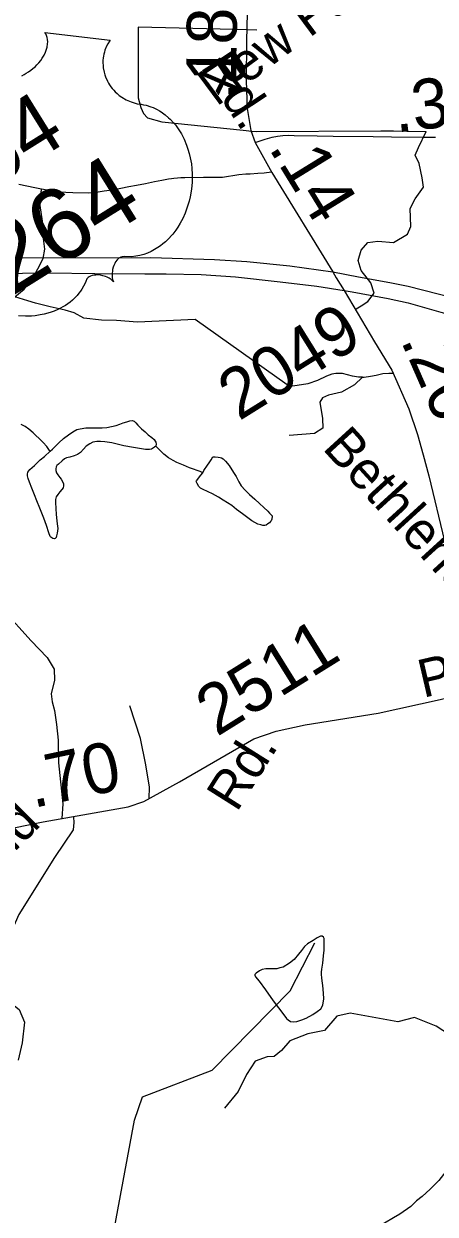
# Model space of a CAD drawing. Extents: x 2001466 to 31450019, y -30647475 to 847247.
# Drawn here: x 2150565 to 2152625, y 729877 to 735833 of the extents above; entities that cross this region are included whole.
import ezdxf

# ---------------------------------------------------------------- set-up
doc = ezdxf.new("R2010")
doc.units = 0
for name, color, linetype in [('Exist Hydrographic Misc Water Feature', 7, 'Continuous'), ('Exist Road Non-System Type 51', 7, 'Continuous'), ('Exist Road Non-System Type 51 Label', 7, 'Continuous'), ('Exist Road Primary US Divided Attributed', 7, 'Continuous'), ('Exist Road Primary US Shield CELL', 7, 'Continuous'), ('Exist Road Primary US Shield Number Label', 7, 'Continuous'), ('Exist Road Secondary Mileage Hundredths English Label', 7, 'Continuous'), ('Exist Road Secondary Type 51 Attributed', 7, 'Continuous'), ('Exist Road Secondary Type 51 Label', 7, 'Continuous'), ('Exist Road Secondary Type 51 Number Label', 7, 'Continuous')]:
    doc.layers.add(name, color=color, linetype=linetype)

msp = doc.modelspace()

# ---------------------------------------------------------------- linework, layer by layer
at = {"layer": 'Exist Hydrographic Misc Water Feature'}
for points in [[(2150696.8, 733694.2), (2150708.7, 733704.6), (2150740.9, 733736.6), (2150764.4, 733758.6), (2150788.4, 733776.9), (2150810.2, 733791.1), (2150830.1, 733803.1), (2150848.3, 733807.2), (2150876.2, 733811.5), (2150938.3, 733811.8), (2150958.2, 733811.7), (2150980.4, 733814), (2151004.4, 733818.1), (2151027.9, 733824.2), (2151046, 733830.5), (2151062.2, 733836.5), (2151081.9, 733842.4), (2151096.2, 733846.4), (2151107.9, 733848.6), (2151118, 733844.7), (2151125.9, 733836.6), (2151136, 733825), (2151154.2, 733806.8), (2151172.3, 733791.1), (2151188.3, 733777.3), (2151206.3, 733763.2), (2151218.4, 733753.3), (2151222.5, 733745.4), (2151226.2, 733739.5), (2151228.5, 733729.5), (2151226.4, 733719.6)], [(2150696.8, 733694.2), (2150694.9, 733698.2), (2150680.8, 733718.2), (2150662.9, 733737.9), (2150642.4, 733758.1), (2150626.4, 733773.9), (2150612.7, 733786.1), (2150590.4, 733805.6), (2150572.5, 733817.7), (2150552.4, 733827.6)], [(2151226.4, 733719.6), (2151220.5, 733715.2), (2151204.9, 733705.4), (2151194.6, 733703.3), (2151174.7, 733703.1), (2151114.7, 733712.6), (2151066.5, 733722.3), (2151006.8, 733736.2), (2150970.3, 733741.7), (2150950.2, 733743.9), (2150930.7, 733743.7), (2150910.4, 733739.4), (2150896.7, 733731.3), (2150877, 733719.3), (2150864.9, 733705.3), (2150848.9, 733689.1), (2150835, 733679), (2150817.1, 733671.2), (2150795.2, 733664.8), (2150778.8, 733660.8), (2150768.7, 733657), (2150757.3, 733646.6), (2150739.4, 733630.6), (2150731.2, 733622.5), (2150727.3, 733616.6), (2150725.7, 733606.7), (2150725.5, 733598.6), (2150729.4, 733586.7), (2150735.5, 733576.9), (2150745.8, 733562.7), (2150751.7, 733554.5), (2150763.8, 733532.8), (2150764, 733528.7), (2150764, 733521), (2150762, 733510.8), (2150755.8, 733502.8), (2150745.8, 733490.9), (2150736.6, 733478.5), (2150728.1, 733466.8), (2150726.3, 733460.6), (2150724, 733452.4), (2150724.5, 733438.6), (2150726.7, 733378.6), (2150731.2, 733346.7), (2150733.1, 733330.6), (2150735.1, 733308.8), (2150733.1, 733284.8), (2150729.2, 733270.8), (2150727.3, 733262.5), (2150723.2, 733258.7), (2150719.5, 733256.8), (2150711.3, 733258.4), (2150701.3, 733264.4), (2150697.4, 733268.7), (2150691.4, 733286.6), (2150679.1, 733322.5), (2150665, 733360.4), (2150646.5, 733410.2), (2150630.3, 733445.9), (2150618.4, 733476.1), (2150605.7, 733510.1), (2150593.8, 733539.9), (2150587.9, 733557.8), (2150583.8, 733571.8), (2150583.4, 733580), (2150585.4, 733589.8), (2150595.5, 733603.7), (2150619.3, 733624), (2150647.4, 733652.3), (2150669.1, 733668), (2150696.8, 733694.2)], [(2151461.4, 733586.7), (2151449.1, 733592.6), (2151433.1, 733598.7), (2151415.5, 733604.6), (2151395, 733612.2), (2151365.2, 733624.4), (2151331, 733638.1), (2151313, 733648.1), (2151289, 733661.8), (2151266.8, 733679.4), (2151244.5, 733701.4), (2151226.4, 733719.6)], [(2151461.4, 733586.7), (2151467.2, 733598.8), (2151485.2, 733624.9), (2151493, 733636.7), (2151503, 733651), (2151512.5, 733667), (2151522.7, 733667.1), (2151538.5, 733665.1), (2151548.8, 733663.1), (2151554.9, 733661.4), (2151562.7, 733657.4), (2151575.2, 733645.3), (2151593.3, 733623.6), (2151615.2, 733587.4), (2151629.3, 733567.8), (2151641.2, 733541.6), (2151653.8, 733521.9), (2151673.8, 733499.8), (2151695.8, 733478.3), (2151721.8, 733454.4), (2151745.8, 733432.5), (2151766.3, 733412.4), (2151786.4, 733394.8), (2151796.1, 733384.8), (2151804.5, 733376.6), (2151808.8, 733370.7), (2151808.4, 733366.7), (2151806.7, 733358.8), (2151806.5, 733354.8), (2151804.3, 733346.6), (2151800.6, 733342.7), (2151794.6, 733336.7), (2151786.6, 733330.6), (2151778.8, 733324.5), (2151772.7, 733322.6), (2151768.8, 733322.4), (2151762.8, 733322.5), (2151752.8, 733326.4), (2151737, 733330.4), (2151706.4, 733346.4), (2151660.5, 733381.7), (2151630.2, 733403.8), (2151606.2, 733423.6), (2151563.9, 733449.5), (2151540.2, 733465.3), (2151510, 733481.2), (2151487.9, 733491), (2151459.6, 733504.6), (2151449.9, 733510.6), (2151441.9, 733518.7), (2151433.5, 733532.5), (2151427.6, 733542.7), (2151429.6, 733546.5), (2151451.8, 733574.8), (2151461.4, 733586.7)], [(2150797.5, 728339.4), (2150837.2, 728663.8), (2150811.2, 728854.7), (2150834.4, 729119.9), (2150809.3, 729195.8), (2150825.3, 729303.8), (2151014.2, 729782.2), (2151119.2, 730347.5), (2151160.2, 730464.8), (2151509.2, 730598.7), (2151899.2, 730994.3), (2152022.2, 731234.5)], [(2151840.3, 730909.8), (2151876.6, 730861.7), (2151880.7, 730855.8), (2151888.7, 730850.2), (2151900.8, 730841.8), (2151916.8, 730840.2), (2151932.8, 730842.3), (2151956.8, 730850.4), (2151978.6, 730858.5), (2152012.6, 730876.9), (2152034.5, 730891), (2152052.2, 730905), (2152062.2, 730922.9), (2152068, 730954.9), (2152065.9, 730982.8), (2152061.6, 731021.1), (2152059.8, 731045), (2152057.7, 731060.7), (2152055.2, 731076.9), (2152055, 731089.1), (2152057.5, 731102.9), (2152062.8, 731132.9), (2152066.5, 731170.9), (2152068.8, 731199), (2152068.6, 731229), (2152068.8, 731244.8), (2152068.2, 731257), (2152066.3, 731263), (2152058.3, 731268.7), (2152054, 731268.9), (2152050.1, 731268.7), (2152034.3, 731260.5), (2152014.6, 731246.5), (2151986.3, 731230.4), (2151970.6, 731216.2), (2151954.8, 731196.3), (2151940.8, 731178.2), (2151919.1, 731152.2), (2151895.1, 731133.9), (2151863.3, 731113.6), (2151847.3, 731109.5), (2151831.3, 731105.5), (2151805.3, 731105.3), (2151777.2, 731105.1), (2151759.1, 731101.4), (2151745, 731095), (2151727.8, 731083), (2151721.6, 731077), (2151721.4, 731073), (2151725.5, 731065.1), (2151743.6, 731043.3), (2151775.8, 730999.5), (2151814.5, 730945.4), (2151840.3, 730909.8)], [(2152845.1, 730401.7), (2152811.7, 730321.1), (2152799.8, 730295.4), (2152769.6, 730243.1), (2152747.9, 730199), (2152722.3, 730154.9), (2152696.4, 730114.7), (2152643.1, 730046.5), (2152599.2, 730002.4), (2152559.5, 729966.2), (2152531.6, 729944.1), (2152503.5, 729915.9), (2152447.9, 729877.3), (2152416.3, 729859.3), (2152370.4, 729833), (2152310.3, 729796.6), (2152241, 729750.3), (2152172.9, 729701.8), (2152139.3, 729683.8), (2152099.3, 729665.5), (2152019.4, 729647.2), (2152007.7, 729642.9)]]:
    msp.add_lwpolyline(points, dxfattribs=at)
at = {"layer": 'Exist Road Non-System Type 51'}
msp.add_line((2151732.6, 735802), (2151684.9, 735803.1), dxfattribs=at)
for points in [[(2151684.9, 735803.1), (2151138.7, 735815.9), (2151138.7, 735600.4), (2151137.7, 735463.2), (2151151, 735414.4), (2151164.3, 735384.4), (2151185.4, 735363.3), (2151256.3, 735342.3), (2151663.1, 735301.5), (2151706.3, 735295.7)], [(2151706.3, 735295.7), (2151731, 735295.1), (2152352.6, 735297.2), (2152416.6, 735297.9), (2152482.7, 735296.5), (2152578.9, 735294.7)], [(2152228.4, 734407.4), (2152253.6, 734422.3), (2152288.3, 734443.1), (2152319.6, 734484.8), (2152302.2, 734537), (2152253.6, 734599.5), (2152239.7, 734648.2), (2152253.6, 734700.3), (2152288.3, 734738.5), (2152336.9, 734745.5), (2152416.8, 734738.5), (2152486.3, 734780.2), (2152503.6, 734818.5), (2152500.2, 734908.8), (2152524.5, 734957.5), (2152566.1, 735016.6), (2152559.2, 735061.7), (2152545.3, 735134.7), (2152524.5, 735176.4), (2152541.8, 735214.7), (2152578.9, 735294.7)], [(2151804.9, 735091.5), (2151769.4, 735086.1), (2151736.2, 735083.9), (2151698.5, 735080.5), (2151676.3, 735080.5), (2151642, 735077.2), (2151560.9, 735064.6), (2151520.9, 735064.2), (2151504.9, 735064.2), (2151464.9, 735063.6), (2151370.9, 735062.7), (2151352.3, 735062.5), (2151334.5, 735061.5), (2151317.2, 735059.8), (2151304.8, 735058.1), (2151289, 735055.8), (2151257, 735049.4), (2151219.1, 735043), (2151175.1, 735032.5), (2151129.1, 735024.1), (2151091.2, 735017.7), (2151019.3, 735002.9), (2150968.4, 734995.4), (2150937.5, 734990), (2150911, 734987.1), (2150888, 734986), (2150810.8, 734987), (2150775.4, 734988.3), (2150751.5, 734990), (2150711.4, 734995.6), (2150653.9, 735006.5)], [(2150520.7, 734466.9), (2150567.2, 734505.8), (2150613.8, 734567.9), (2150635.9, 734607.8), (2150662.5, 734658.8), (2150671.4, 734705.4), (2150664.7, 734758.6), (2150659.8, 734801), (2150659.8, 734845.3), (2150647.5, 734924.1), (2150650, 734968.4), (2150653.9, 735006.5)], [(2150653.9, 735006.5), (2150621.2, 735012.7), (2150540.9, 735029.9)], [(2152260.1, 734064.8), (2152240.3, 734064.6), (2152211, 734069.7), (2152160, 734083), (2152126.8, 734083), (2152106.8, 734080.8), (2152080.1, 734070.8), (2152035.8, 734048.7), (2151986.6, 734031.4), (2151912.6, 734020.1), (2151900.3, 734022), (2151883.2, 734026.5), (2151422.8, 734353.6), (2151314.6, 734349.1), (2151134.9, 734340.5), (2151029.1, 734347.9), (2150955.2, 734350.3), (2150866.6, 734360.2), (2150817.4, 734387.3), (2150773.1, 734399.6), (2150696.8, 734416.8), (2150624.8, 734435.9), (2150584.9, 734447), (2150520.7, 734466.9)], [(2152260.1, 734064.8), (2152268.5, 734064.8), (2152301.7, 734070.8), (2152328.7, 734075.7), (2152363.2, 734083.1), (2152392.7, 734085.6), (2152410.3, 734085.9)], [(2152260.1, 734064.8), (2152220.4, 734026.5), (2152156.4, 733989.6), (2152090, 733974.8), (2152060.4, 733962.5), (2152048.1, 733940.3), (2152060.3, 733859), (2152062.5, 733810.2), (2152021, 733782.7), (2151893, 733772.9)], [(2150338.3, 733100.9), (2150377.7, 733024.6), (2150463.8, 732899.1), (2150601.5, 732746.5), (2150682.7, 732662.8), (2150717.1, 732603.8), (2150719.6, 732549.6), (2150702.4, 732480.7), (2150707.3, 732441.3), (2150719.6, 732397), (2150729.4, 732328.1), (2150736.8, 732249.3), (2150739.3, 732136.1), (2150761.4, 731930.8), (2150756.2, 731856.8)], [(2151192.7, 731957.3), (2151194.3, 732014.5), (2151177.1, 732125.3), (2151150, 732258.2), (2151097, 732420.5)], [(2150814.5, 731863.8), (2150815.7, 731836.6), (2150813.1, 731800.9), (2150718.5, 731662.8), (2150540, 731377.5), (2150441.7, 731156), (2150407.2, 731079.5), (2150399.8, 731027.8), (2150417.1, 731000.7), (2150542.5, 730902.3), (2150569.6, 730838.3), (2150557.3, 730734.9), (2150537.8, 730648)], [(2153116.6, 730761.4), (2153003.3, 730759.7), (2152919.3, 730749), (2152871.3, 730751.9), (2152826, 730749.9), (2152725.6, 730755.8), (2152629.4, 730818.9), (2152521.1, 730862.2), (2152438.4, 730840.6), (2152200, 730883.9), (2152133, 730868.2), (2152070, 730797.2), (2151987.3, 730779.5), (2151896.7, 730744), (2151854.9, 730696.7), (2151819.4, 730667.1), (2151784, 730665.1), (2151722.9, 730643.4), (2151680, 730576.4), (2151638.8, 730491.6), (2151569.4, 730408.2)]]:
    msp.add_lwpolyline(points, dxfattribs=at)
at = {"layer": 'Exist Road Primary US Divided Attributed'}
for points in [[(2148258.9, 734664.9), (2148680.6, 734662.8), (2151201.1, 734664.5), (2151520.3, 734654.3), (2151681.6, 734643.4), (2151896.7, 734622.6), (2152112.4, 734591.4)], [(2148292, 734581.9), (2150165.8, 734580.5), (2150688.3, 734587.2), (2150920.6, 734583.5), (2151170.8, 734582.6), (2151277.7, 734582.7), (2151454.1, 734579.2), (2151625.7, 734566.5), (2151848.6, 734542.6), (2152031.9, 734520.4), (2152168.5, 734498)], [(2152112.4, 734591.4), (2152240.6, 734567.5), (2152397.5, 734539.1), (2152490.1, 734519.8), (2152640.4, 734482.5), (2152749.5, 734453.1), (2152903.7, 734408.2), (2153058.8, 734357), (2153266.2, 734288.2), (2153500.8, 734203.2)], [(2152168.5, 734498), (2152209.1, 734491.3), (2152389.2, 734459.3), (2152490.1, 734436.4), (2152652.3, 734390.8), (2152894.5, 734323.9), (2153075.3, 734263.5), (2153225.8, 734214.9), (2153330.5, 734176.5), (2153443.9, 734138.1)]]:
    msp.add_lwpolyline(points, dxfattribs=at)
at = {"layer": 'Exist Road Primary US Shield CELL'}
msp.add_lwpolyline([(2150555.6, 735573.3), (2150568, 735579.8), (2150577.9, 735585.5), (2150589.6, 735593.1), (2150600.2, 735600.5), (2150610.6, 735608.8), (2150621.7, 735618.6), (2150630.3, 735627), (2150641.3, 735638.6), (2150650.5, 735650.3), (2150658.1, 735661.3), (2150667.2, 735676.8), (2150673.9, 735690.5), (2150677.9, 735701.9), (2150682, 735716.6), (2150684.5, 735732.7), (2150685, 735743.6), (2150683.9, 735753.8), (2150682.2, 735764.2), (2150678.9, 735774.3), (2150675.2, 735782.6), (2150671.3, 735789.2), (2150997.9, 735751.3), (2150994, 735746.1), (2150985.8, 735732.9), (2150979.8, 735721.5), (2150971.4, 735701.6), (2150968.6, 735691.8), (2150965.9, 735681.7), (2150964, 735671.5), (2150962.5, 735662.2), (2150961.7, 735649.5), (2150961.5, 735637.2), (2150962, 735624.1), (2150963.1, 735613.2), (2150967.3, 735591.4), (2150971, 735578.3), (2150974.8, 735567.6), (2150984.4, 735546.6), (2150989.5, 735536.9), (2150995.2, 735527.7), (2151001.8, 735518.4), (2151008.5, 735509.6), (2151016.2, 735501), (2151023, 735493.4), (2151032.2, 735484.7), (2151043.6, 735475), (2151055.7, 735466.2), (2151077.5, 735453.5), (2151102.4, 735442.1), (2151118.3, 735437), (2151133.1, 735433.3), (2151153.7, 735430.3), (2151165, 735428.4), (2151178.6, 735425.3), (2151202.1, 735417.9), (2151212.3, 735413.9), (2151223.2, 735409), (2151233.7, 735403.6), (2151244.6, 735397.5), (2151253.8, 735391.9), (2151273.2, 735378), (2151290.1, 735363.3), (2151298.6, 735355.4), (2151316, 735336.5), (2151324.2, 735326.9), (2151338.8, 735307), (2151354.7, 735281.8), (2151367.7, 735256.6), (2151380.6, 735225.8), (2151387.3, 735206.7), (2151393.7, 735183.6), (2151398.7, 735163.3), (2151404.2, 735132.2), (2151406.6, 735108.6), (2151408.3, 735080.3), (2151408.4, 735062.6), (2151407.8, 735043.2), (2151406.1, 735020.4), (2151403.1, 734995.2), (2151398, 734967.5), (2151393.1, 734946.4), (2151385.6, 734920.6), (2151380.6, 734905.6), (2151372.8, 734885.4), (2151361, 734859.4), (2151348.3, 734835.6), (2151336.8, 734816.4), (2151325.9, 734800.7), (2151311.1, 734781.3), (2151284.4, 734752.3), (2151274.2, 734742.5), (2151261.6, 734731.8), (2151249.4, 734722.4), (2151237.2, 734713.7), (2151220.2, 734703.1), (2151202.5, 734693.9), (2151185.1, 734686.3), (2151166.3, 734679.4), (2151145.6, 734673.7), (2151126, 734670.1), (2151105.1, 734668), (2151067.5, 734668.2), (2151057.1, 734667.5), (2151052, 734665.9), (2151041.2, 734659.9), (2151032.7, 734651.7), (2151025.2, 734641.5), (2151021.1, 734634.5), (2151016.4, 734624.2), (2151013.2, 734615.4), (2151010.2, 734603.6), (2151008.7, 734594.5), (2151007.7, 734587.4), (2151007.5, 734570.7), (2151008.4, 734563.3), (2151010.1, 734554.2), (2151014.4, 734541.8), (2151002.4, 734553.3), (2150992.8, 734559.9), (2150983.3, 734564.7), (2150974.2, 734568.6), (2150961.2, 734572.6), (2150950.2, 734574.9), (2150937.8, 734576.5), (2150925.7, 734576.3), (2150916.5, 734575.5), (2150908.5, 734574), (2150899.4, 734571), (2150892.6, 734567.5), (2150887.4, 734564.1), (2150881.2, 734557.9), (2150875.8, 734544.6), (2150870.4, 734532.4), (2150864.2, 734519.7), (2150856.1, 734505.7), (2150849.7, 734496), (2150841.7, 734485.3), (2150831.9, 734473.5), (2150820.7, 734461.6), (2150808.6, 734450.3), (2150797.7, 734440.9), (2150785.4, 734431.6), (2150773.9, 734423.9), (2150761.6, 734416.4), (2150749.5, 734410.1), (2150735.5, 734403), (2150717.5, 734395.2), (2150701.9, 734389.8), (2150685, 734384.7), (2150667.3, 734380.1), (2150647.7, 734376.3), (2150622.5, 734372.5), (2150604.2, 734371), (2150574.7, 734370), (2150538.1, 734371.8)], dxfattribs=at)
at = {"layer": 'Exist Road Secondary Type 51 Attributed'}
for points in [[(2151689.9, 736168.2), (2151679.9, 735748.3), (2151677.8, 735547.2), (2151683.1, 735409), (2151701.9, 735300.1), (2151723.6, 735239)], [(2151723.6, 735239), (2151773.2, 735256.1), (2151808.4, 735266), (2151835.9, 735271.4), (2151862.8, 735274.7), (2151892.4, 735275.1), (2151919.2, 735273.9), (2152033.7, 735272.6), (2152113.9, 735271.6), (2152314.2, 735269.9), (2152406.7, 735267.5), (2152565, 735265.2), (2152626.1, 735266.7)], [(2151723.6, 735239), (2151806.5, 735088.6), (2152112.4, 734591.4)], [(2152112.4, 734591.4), (2152129.9, 734562.9), (2152168.5, 734498)], [(2152168.5, 734498), (2152320.3, 734242.5), (2152408.2, 734100.1), (2152493, 733907.4), (2152536.9, 733777.6), (2152564.1, 733677.1), (2152593.4, 733572.3), (2152670.8, 733244.6)], [(2149280.5, 731475), (2149315.6, 731509.5), (2149367.9, 731544.1), (2149667.2, 731616.3), (2150164.2, 731738.8), (2150662.8, 731840.4), (2151087.1, 731914.8), (2151166.7, 731943), (2151344.5, 732040.4), (2151716.5, 732255.1), (2151829.5, 732293.8), (2151973.9, 732325.2), (2152339.1, 732383.9), (2152648.9, 732453), (2152802.2, 732490.7)]]:
    msp.add_lwpolyline(points, dxfattribs=at)

# ---------------------------------------------------------------- texts
at = {"layer": 'Exist Road Non-System Type 51 Label'}
msp.add_text('Parrish', height=190, rotation=13.09694, dxfattribs=at).set_placement((2152564.4, 732460.3))
at = {"layer": 'Exist Road Primary US Shield Number Label'}
for s, height, p in [('64', 310, (2150397.6, 735002.1)), ('264', 360, (2150499.1, 734464.7))]:
    msp.add_text(s, height=height, rotation=31.91803, dxfattribs=at).set_placement(p)
at = {"layer": 'Exist Road Secondary Mileage Hundredths English Label'}
for s, rotation, p in [('.18', 89.40373, (2151627.6, 735448.8)), ('.38', 6.90602, (2152428.5, 735288.1)), ('.14', 301.59591, (2151788.1, 735212.4)), ('.26', 293.74496, (2152450.2, 734249.7)), ('.70', 12.03761, (2150611.8, 731908.9))]:
    msp.add_text(s, height=250, rotation=rotation, dxfattribs=at).set_placement(p)
at = {"layer": 'Exist Road Secondary Type 51 Label'}
for s, rotation, p in [('New Faison St.', 36.53622, (2151529.5, 735415.8)), ('Rd.', 303.36391, (2151446, 735617.6)), ('Bethlehem', 312.40621, (2152056, 733707.9)), ('Rd.', 57.73572, (2151631.2, 731884.3)), ('K-Held', 44.9138, (2150107.2, 731277.7))]:
    msp.add_text(s, height=190, rotation=rotation, dxfattribs=at).set_placement(p)
at = {"layer": 'Exist Road Secondary Type 51 Number Label'}
for s, p in [('2049', (2151642.3, 733843.7)), ('2511', (2151531.7, 732264))]:
    msp.add_text(s, height=250, rotation=31.91803, dxfattribs=at).set_placement(p)

doc.saveas('drawing.dxf')
